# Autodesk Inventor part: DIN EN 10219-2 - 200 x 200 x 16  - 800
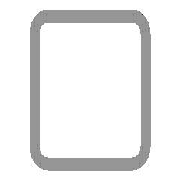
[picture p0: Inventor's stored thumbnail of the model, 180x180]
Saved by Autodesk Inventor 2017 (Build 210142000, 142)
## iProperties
Created: 2016-02
Part Number: DIN EN 10219-2 - 200 x 200 x 16  - 800
Material: Steel, Mild
Description: Cold formed welded structural hollow sections of non-alloy and fine grain structural steel
Document SubType Name: Modeling
Standard: DIN
Designer: iusti
Standard Revision: 2006-07
Standards Organization: DIN
Language: en-US
Size Designation: 200 x 200 x 16
Categories: <MemberInstance><Categories><Category DisplayName="Structural Shapes" InternalName="089c4875-fa83-4c05-b084-43b9cc11f5ed" Mnemonic="GRDR"><CategoryParameter Dis
Stock Number: 200 x 200 x 16
Mass: 67053.1 g
Surface Area: 10890.8 cm^2
Volume: 8541.79 cm^3
Density: 7.85 g/cm^3
Appearance: Semi-Polished
G_L: 800.000 mm
G_W: 200.000 mm
G_H: 200.000 mm
+D725846C-1BBA-43C5-9142-E43B5E702370+CUTDETAIL1: Cut
+61ECF291-9442-4532-A0A0-FF6287E9C23A+CUTDETAIL2: Cut
IsCustomPart: 1
_CCFamilyMember: 103
_CCFamilyDisplayName: DIN EN 10219-2 (Square Hollow Section - Cold Formed) - Cold formed welded structural hollow sections of non-alloy and fine grain structural steel
_FrameMemberDoc: Frame Member File
_Version: 15.0.0
_GetPNFromCC: 1
Author: iusti
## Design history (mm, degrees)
node "Start plane"
node "End plane"
sketch "Sketch"
  geometry: L1 (-100, -52)-(-100, 52); L2 (-52, 100)-(52, 100); L3 (100, 52)-(100, -52); L4 (52, -100)-(-52, -100); L5 (-52, 84)-(52, 84); L6 (84, 52)-(84, -52); L7 (52, -84)-(-52, -84); L8 (-84, -52)-(-84, 52); L9 (0, 153.918)-(0, -153.918) reference; L10 (-153.918, 0)-(153.918, 0) reference; A1 r 48 centre (-52, -52) between (-100, -52) and (-52, -100); A2 r 48 centre (-52, 52) between (-52, 100) and (-100, 52); A3 r 48 centre (52, 52) between (100, 52) and (52, 100); A4 r 48 centre (52, -52) between (52, -100) and (100, -52); A5 r 32 centre (-52, 52) between (-52, 84) and (-84, 52); A6 r 32 centre (52, 52) between (84, 52) and (52, 84); A7 r 32 centre (52, -52) between (52, -84) and (84, -52); A8 r 32 centre (-52, -52) between (-84, -52) and (-52, -84)
  constraints: 16 end point, 16 point on circle, 8 centre point, 8 tangent, 4 parallel, 3 equal radius, 2 perpendicular, 7 other
  dimensions: "d7" = 48 radius of A1 (= G_IR); "d10" = 200 distance between parallel lines of L2 L4 (= G_H); "d11" = 200 distance between parallel lines of L1 L3 (= G_W); "d12" = 16 distance between parallel lines of L3 L6 (= G_T); "d15" = 100 distance between parallel lines of L2 L10 (= 0.5 x d10); "d16" = 100 distance between parallel lines of L9 L3 (= 0.5 x d11)
extrude "Body" new body sketch "Sketch" stored distance "d3" = 800 (= G_L); taper "d4" = 0 deg
node "Driven Length"
  sketch "Sketch3"
    geometry: L1 (0, 0)-(10, 0) reference
    constraints: 2 end point, 1 horizontal
  workplane "Work Plane3"
  sketch "Sketch4"
    geometry: L1 (-2, 100)-(12, 100) reference; L2 (-2, 900)-(12, 900) reference
    dimensions: "d18" = 800 distance between parallel lines of L1 L2 (derived)
workplane "Work Plane4"
split "Split1"
workplane "Work Plane5"
split "Split2"
body "Solid1"
other parameters: "G_W" = 200 [user parameter; used in 1 equation term], "G_H" = 200 [user parameter; used in 1 equation term], "G_T" = 16 [user parameter; used in 1 equation term], "G_IR" = 48 [user parameter; used in 1 equation term], "G_L" = 800 (= d18) [user parameter; used in 1 equation term], "d17" = 90 deg
